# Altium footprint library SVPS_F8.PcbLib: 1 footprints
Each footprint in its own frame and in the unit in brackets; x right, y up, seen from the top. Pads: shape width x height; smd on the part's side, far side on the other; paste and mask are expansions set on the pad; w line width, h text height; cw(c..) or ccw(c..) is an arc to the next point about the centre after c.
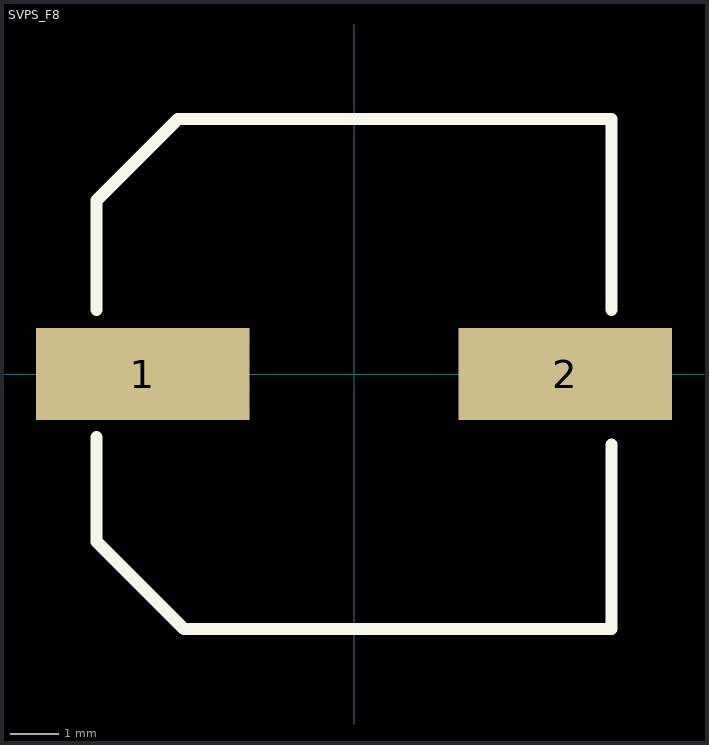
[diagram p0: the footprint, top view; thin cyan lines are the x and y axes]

## SVPS_F8 [mm] "SANYO SVPS_F8"
height 8
pads (2):
  rect 4.4x1.9 smd: 1(-4.35,0) 2(4.35,0)
Top Overlay:
  lines w0.254: -5.3,-1.3 -5.3,-3.45 -3.5,-5.25 5.3,-5.25 5.3,-1.45 ; -5.3,1.325 -5.3,3.575 -3.625,5.25 5.3,5.25 5.3,1.325
M5 Assembly Top:
  text ".Designator" at -0.508,0 h1.02
3D body: height 8, standoff 0, extent -5.25,-5.225 5.325,5.2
